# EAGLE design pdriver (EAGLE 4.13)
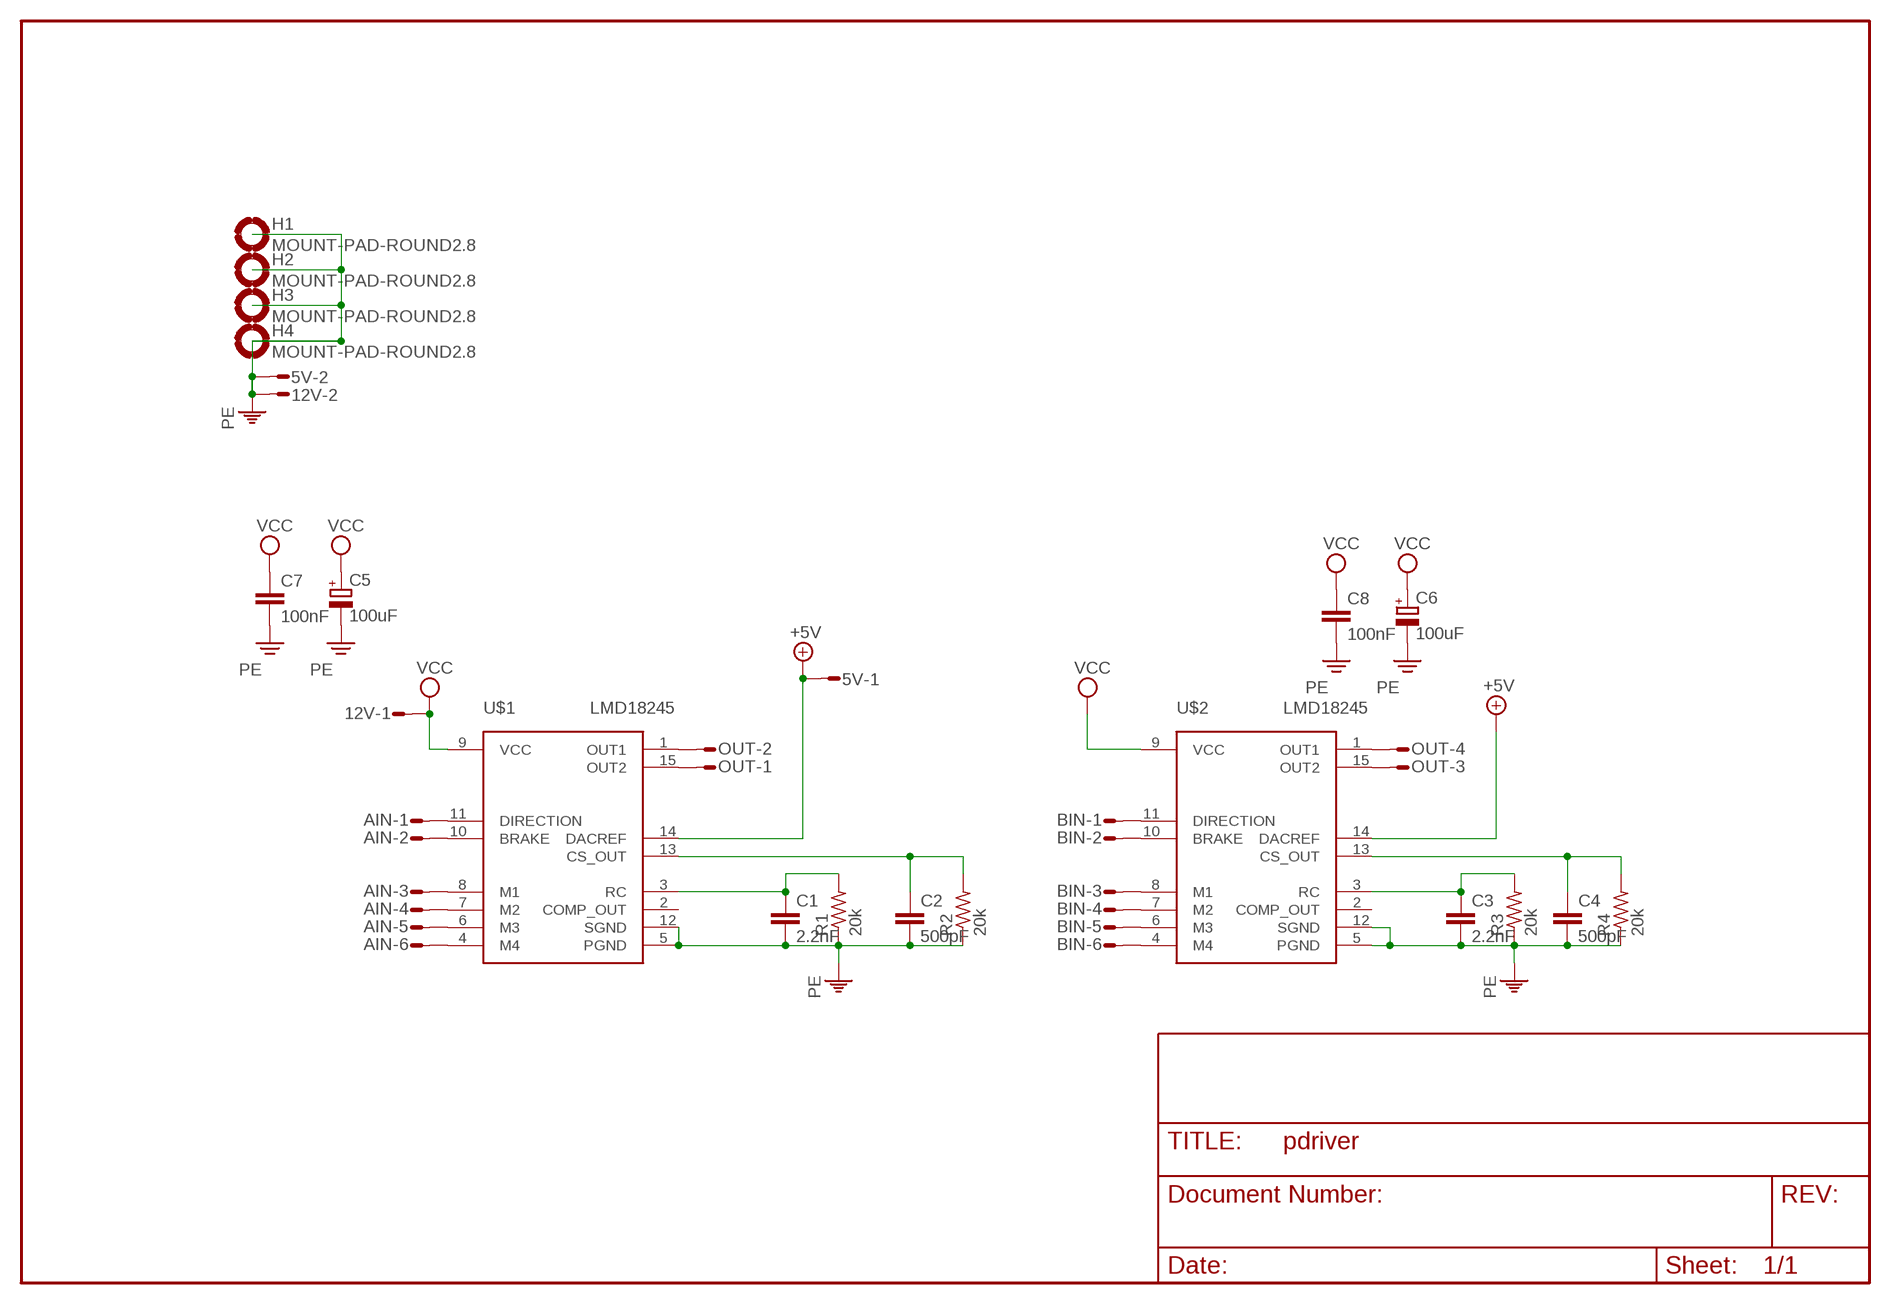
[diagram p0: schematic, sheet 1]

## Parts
5V  S02P  [S02P]
12V  S02P  [S02P]
AIN  S06P  [S06P]
BIN  S06P  [S06P]
C1  2.2nF  C-EU050-030X075  [C050-030X075]
C2  500pF  C-EU050-030X075  [C050-030X075]
C3  2.2nF  C-EU050-030X075  [C050-030X075]
C4  500pF  C-EU050-030X075  [C050-030X075]
C5  100uF  CPOL-EUE5-10.5  [E5-10,5]
C6  100uF  CPOL-EUE5-10.5  [E5-10,5]
C7  100nF  C-EU050-030X075  [C050-030X075]
C8  100nF  C-EU050-030X075  [C050-030X075]
H1  MOUNT-PAD-ROUND2.8  [2,8-PAD]
H2  MOUNT-PAD-ROUND2.8  [2,8-PAD]
H3  MOUNT-PAD-ROUND2.8  [2,8-PAD]
H4  MOUNT-PAD-ROUND2.8  [2,8-PAD]
OUT  MT6-4  [MT6-4]
R1  20k  R-US_0207/12  [0207/12]
R2  20k  R-US_0207/12  [0207/12]
R3  20k  R-US_0207/12  [0207/12]
R4  20k  R-US_0207/12  [0207/12]
U$1  LMD18245  [TA15A]
U$2  LMD18245  [TA15A]

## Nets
+5V: 5V.1 U$1.14(DACREF) U$2.14(DACREF)
N$1: OUT.1 U$1.15(OUT2)
N$2: C1.1 R1.2 U$1.3(RC)
N$3: C2.1 R2.2 U$1.13(CS_OUT)
N$4: OUT.2 U$1.1(OUT1)
N$5: C3.1 R3.2 U$2.3(RC)
N$6: C4.1 R4.2 U$2.13(CS_OUT)
N$7: OUT.4 U$2.1(OUT1)
N$8: OUT.3 U$2.15(OUT2)
N$9: AIN.1 U$1.11(DIRECTION)
N$10: AIN.2 U$1.10(BRAKE)
N$11: AIN.3 U$1.8(M1)
N$12: AIN.4 U$1.7(M2)
N$13: AIN.5 U$1.6(M3)
N$14: AIN.6 U$1.4(M4)
N$15: BIN.1 U$2.11(DIRECTION)
N$16: BIN.2 U$2.10(BRAKE)
N$17: BIN.3 U$2.8(M1)
N$18: BIN.4 U$2.7(M2)
N$19: BIN.5 U$2.6(M3)
N$20: BIN.6 U$2.4(M4)
PE: 5V.2 12V.2 C1.2 C2.2 C3.2 C4.2 C5.- C6.- C7.2 C8.2 H1.B2,8(MOUNT) H2.B2,8(MOUNT) H3.B2,8(MOUNT) H4.B2,8(MOUNT) R1.1 R2.1 R3.1 R4.1 U$1.5(PGND) U$1.12(SGND) U$2.5(PGND) U$2.12(SGND)
VCC: 12V.1 C5.+ C6.+ C7.1 C8.1 U$1.9(VCC) U$2.9(VCC)
Unconnected: U$1.2(COMP_OUT) U$2.2(COMP_OUT)

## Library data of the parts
5V 12V = con-amp-mt:S02P: AMP MT CONNECTOR
AIN BIN = con-amp-mt:S06P: AMP MT CONNECTOR
C1-C4 C7 C8 = rcl:C-EU: CAPACITOR, European symbol
C5 C6 = rcl:CPOL-EU: POLARIZED CAPACITOR, European symbol
H1-H4 = holes:MOUNT-PAD-ROUND: MOUNTING PAD, round
OUT = con-amp-mt6:MT6-4: AMP MT6 CONNECTOR
R1-R4 = rcl:R-US_: RESISTOR, American symbol
U$1 U$2 = linear:LMD18245

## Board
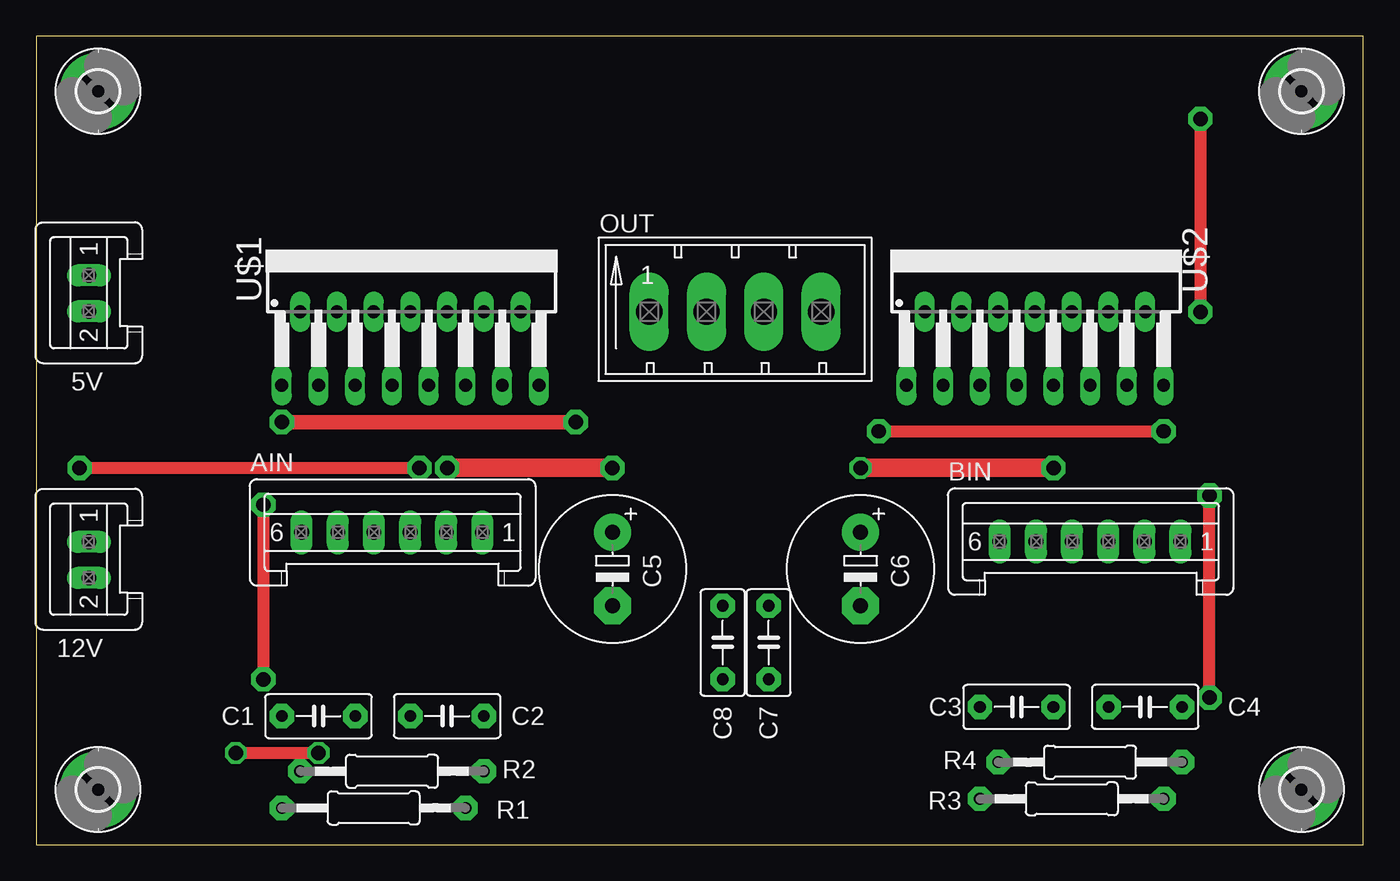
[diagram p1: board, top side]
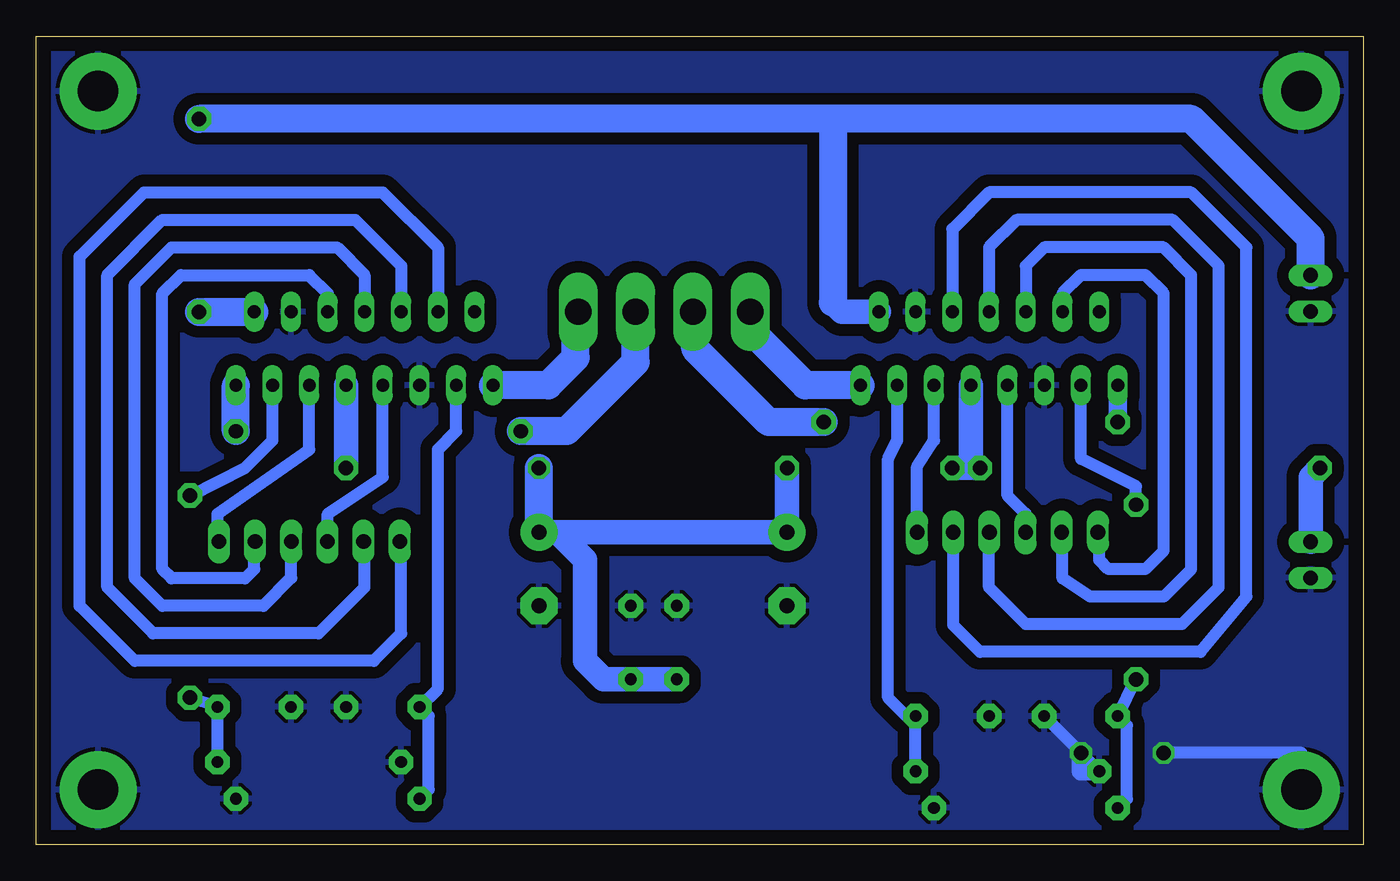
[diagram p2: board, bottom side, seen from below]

Size 91.75 x 55.87 mm. Coordinates in mm from the lower left corner, seen from the top.
Outline: 0,0 91.75,0 91.75,55.87 0,55.87 0,0
Copper layers (1*16): Top 0.035mm / dielectric 1.5mm / Bottom 0.035mm
Design rules "default": minimum track width 32mil, minimum drill 0.8mm, track to track 24mil, track to pad 24mil, pad to pad 8mil, via to via 8mil, smd to smd 8mil, copper to edge 40mil, drill to drill 8mil, minimum pad ring 10mil, minimum via ring 8mil, stop-mask expansion 4mil, vias tented up to drill 0mil, thermal gap 10mil

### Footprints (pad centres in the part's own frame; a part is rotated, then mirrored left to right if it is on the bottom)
S02P = drill 1.016 long: 1 1.25,0; 2 -1.25,0
S06P = drill 1.016 long: 1 6.25,0; 2 3.75,0; 3 1.25,0; 4 -1.25,0; 5 -3.75,0; 6 -6.25,0
C050-030X075 = drill 0.813 pad 1.676 octagon: 1 -2.54,0; 2 2.54,0
E5-10,5 = drill 1.016 pad 2.54 round: + -2.54,0 | drill 1.016 pad 2.54 octagon: - 2.54,0
2,8-PAD = drill 2.8 pad 5.334 round: B2,8 0,0
MT6-4 = drill 1.803 long: 1 2.54,0; 2 6.502,0; 3 10.465,0; 4 14.427,0
0207/12 = drill 0.813 pad 1.676 octagon: 1 -6.35,0; 2 6.35,0
TA15A = drill 0.889 long: 1 -8.89,-6.35; 2 -7.62,-1.27; 3 -6.35,-6.35; 4 -5.08,-1.27; 5 -3.81,-6.35; 6 -2.54,-1.27; 7 -1.27,-6.35; 8 0,-1.27; 9 1.27,-6.35; 10 2.54,-1.27; 11 3.81,-6.35; 12 5.08,-1.27; 13 6.35,-6.35; 14 7.62,-1.27; 15 8.89,-6.35

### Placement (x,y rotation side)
5V  3.65,38.09 90 top
12V  3.65,19.68 90 top
AIN  24.6,21.58 0 top
BIN  72.86,20.95 0 top
C1  19.52,8.88 0 top
C2  28.41,8.88 180 top
C3  67.78,9.52 0 top
C4  76.67,9.52 180 top
C5  39.84,19.04 270 top
C6  56.98,19.04 270 top
C7  50.63,13.96 90 top
C8  47.46,13.96 90 top
H1  4.28,52.06 0 top
H2  4.28,3.8 0 top
H3  87.47,3.8 0 top
H4  87.47,52.06 0 top
OUT  39.84,36.83 0 top
R1  23.33,2.54 180 top
R2  24.6,5.07 0 top
R3  71.59,3.17 180 top
R4  72.86,5.71 0 top
U$1  25.87,38.09 0 top
U$2  69.05,38.09 0 top

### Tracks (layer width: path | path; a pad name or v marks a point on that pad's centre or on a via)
+5V  (via drill 1 pad 1.68)
  Top 0.813: v80.48,50.16 v80.48,36.83
  Bottom 1.676: 36.66,37.46 36.03,36.83 U$1.14
  Bottom 1.93: v80.48,36.83 U$2.14 | 5V.1 3.65,41.91 11.9,50.16 36.66,50.16 | 36.66,50.16 v80.48,50.16 | 36.66,50.16 36.66,37.46
N$1
  Bottom 1.93: U$1.15 38.57,31.75 42.38,35.55 OUT.1
N$2  (via drill 1 pad 1.68)
  Top 0.813: v15.71,11.43 v15.71,23.49
  Bottom 0.813: v15.71,23.49 15.71,24.76 19.52,26.67 U$1.3 | v15.71,11.43 C1.1 16.34,8.25 16.34,3.17 R1.2
N$3
  Bottom 0.813: U$1.13 32.22,27.93 32.85,26.67 32.85,10.15 31.59,8.88 C2.1 R2.2
N$4  (via drill 1 pad 1.68)
  Top 1.016: v16.98,29.21 v37.3,29.21
  Bottom 1.016: 46.19,36.83 OUT.2
  Bottom 1.27: v16.98,29.21 U$1.1
  Bottom 1.93: v37.3,29.21 41.11,29.21 46.19,34.28 46.19,36.83
N$5
  Bottom 0.813: U$2.3 62.7,28.57 63.97,27.3 63.97,10.79 C3.1 64.61,8.88 64.61,3.8 R3.2
N$6  (via drill 1 pad 1.68)
  Top 0.813: v81.12,10.15 v81.12,24.12
  Bottom 0.813: U$2.13 75.4,27.93 77.31,26.03 v81.12,24.12 | v81.12,10.15 C4.1 R4.2
N$7
  Bottom 1.016: 54.45,36.83 OUT.4
  Bottom 1.93: U$2.1 56.35,31.75 54.45,33.65 54.45,36.83
N$8  (via drill 1 pad 1.68)
  Top 0.813: v58.25,28.57 v77.94,28.57
  Bottom 1.93: OUT.3 50.3,33.34 55.08,28.57 v58.25,28.57 | v77.94,28.57 U$2.15
N$9
  Bottom 0.813: AIN.1 30.85,26.13 29.68,27.93 U$1.11
N$10
  Bottom 0.813: AIN.2 28.35,15.18 26.5,13.33 11.27,13.33 8.09,17.14 8.09,41.27 11.9,45.08 25.87,45.08 28.41,42.54 U$1.10
N$11
  Bottom 0.813: U$1.8 25.87,41.27 23.96,43.17 13.17,43.17 10,40 10,17.78 12.54,15.24 23.33,15.24 25.87,17.78 25.87,21.58 AIN.3
N$12
  Bottom 0.813: AIN.4 23.35,22.87 24.6,24.12 U$1.7
N$13
  Bottom 0.813: U$1.6 23.33,40 22.06,41.27 13.81,41.27 11.9,39.36 11.9,19.04 13.81,17.14 18.88,17.14 20.79,18.41 20.79,21.58 AIN.5
N$14
  Bottom 0.813: U$1.4 20.79,38.09 19.52,39.36 15.08,39.36 13.81,38.09 13.81,20.32 15.08,19.04 17.61,19.04 18.25,19.68 18.25,21.58 AIN.6
N$15
  Bottom 0.813: U$2.11 72.86,27.3 79.21,22.86 79.21,20.95 BIN.1
N$16
  Bottom 0.813: U$2.10 71.59,38.09 72.86,39.36 81.75,39.36 83.02,38.09 83.02,19.04 82.39,18.41 77.31,18.41 76.67,19.04 76.67,20.95 BIN.2
N$17
  Bottom 0.813: BIN.3 74.11,18.43 76.04,16.5 83.02,16.5 84.93,18.41 84.93,38.73 82.39,41.27 70.96,41.27 69.05,39.36 U$2.8
N$18
  Bottom 0.813: U$2.7 67.78,25.39 71.59,22.86 71.59,20.95 BIN.4
N$19
  Bottom 0.813: U$2.6 66.51,40 69.69,43.17 83.02,43.17 86.83,39.36 86.83,17.78 83.66,14.6 72.23,14.6 69.05,17.78 69.05,20.95 BIN.5
N$20
  Bottom 0.813: BIN.6 66.51,20.95 66.51,14.6 68.42,12.69 84.93,12.69 88.73,16.5 88.73,40.64 84.29,45.08 67.78,45.08 63.97,41.27 U$2.4
PE  (via drill 1)
  Top 0.813: v13.81,6.34 v19.52,6.34
  Bottom 0.813: R2.1 v19.52,6.34 C1.2 | v13.81,6.34 4.28,6.34 4.28,3.17
  Bottom 1.27: R2.1 19.52,5.07 v19.52,6.34
  pour Bottom (isolate 0.813): 0.47,55.88 0.47,0.63 91.28,0.63 91.28,55.88
VCC  (via drill 1, 1 pad 1.68)
  Top 0.813: v3.01,26.03 v26.5,26.03
  Top 1.27: v28.41,26.03 v39.84,26.03 | v56.98,26.03 v70.32,26.03
  Bottom 0.813: v26.5,26.03 27.14,26.03
  Bottom 1.27: C6.+ 55.71,21.58
  Bottom 1.676: 27.14,26.03 U$1.9 | v70.32,26.03 U$2.9 | v26.5,26.03 v28.41,26.03 | v39.84,26.03 C5.+ C6.+ | 55.71,21.58 53.81,19.68 53.81,12.69 52.54,11.43 C7.1 C8.1 | 12V.1 3.65,25.39 v3.01,26.03
  Bottom 1.93: C6.+ v56.98,26.03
